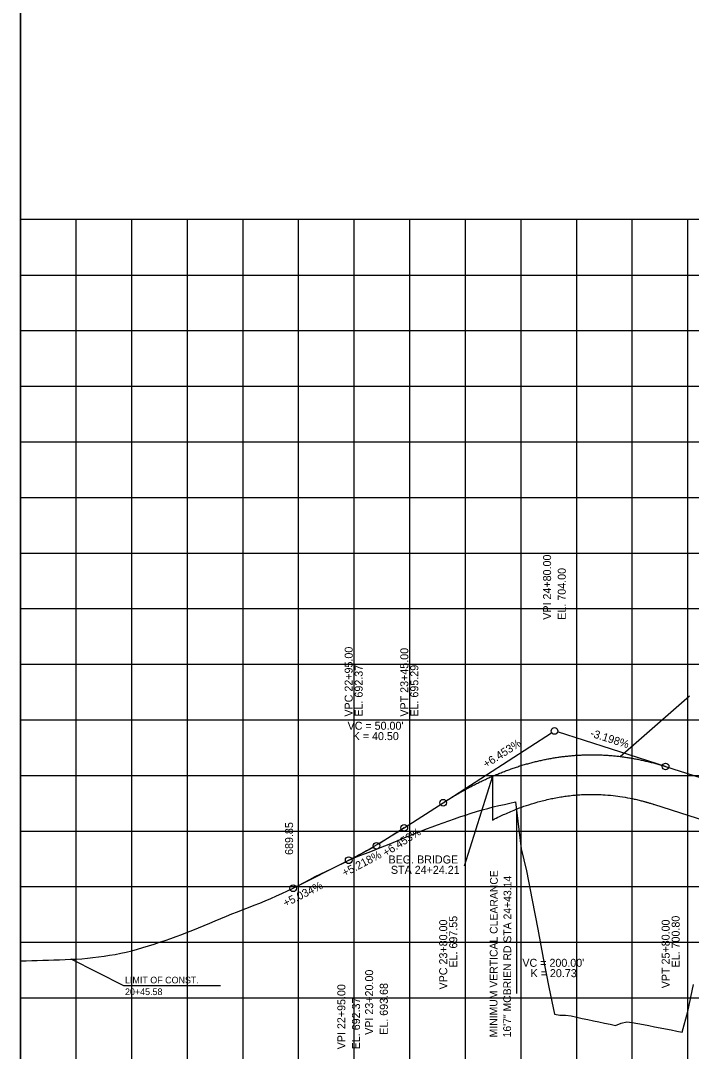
# Model space of a CAD drawing. Extents: x -7164 to 2214450, y -19642 to 253469.
# Drawn here: x 0 to 603, y -8748 to -7821 of the extents above; entities that cross this region are included whole.
import ezdxf

# ---------------------------------------------------------------- set-up
doc = ezdxf.new("R2010")
doc.units = 0
for name, color, linetype in [('DESIGN - PROFILE - Proposed', 7, 'Continuous'), ('DESIGN - PROFILE - Proposed Curve Text', 7, 'Continuous'), ('DESIGN - PROFILE - Proposed Text', 7, 'Continuous'), ('DESIGN - SCRATCH - User 1', 7, 'Continuous'), ('DESIGN - SHEET - Light Grid', 7, 'Continuous'), ('SURVEY - PROFILE - Ground Line with Text', 7, 'Continuous')]:
    doc.layers.add(name, color=color, linetype=linetype)

msp = doc.modelspace()

# ---------------------------------------------------------------- linework, layer by layer
at = {"layer": 'DESIGN - PROFILE - Proposed'}
for p, q in [((580, -8491.98), (660, -8517.56)), ((580, -8491.98), (660, -8517.56)), ((424.21, -8500.71), (424.21, -8540.08)), ((424.21, -8500.71), (424.21, -8540.08)), ((345, -8547.11), (380, -8524.53)), ((345, -8547.11), (380, -8524.53)), ((569.15, -8525.91), (654.21, -8553.11)), ((569.15, -8525.91), (654.21, -8553.11)), ((245, -8601.46), (295, -8576.28)), ((245, -8601.46), (295, -8576.28)), ((179.86, -8689.25), (92.85, -8689.25)), ((179.86, -8689.25), (92.85, -8689.25))]:
    msp.add_line(p, q, dxfattribs=at)
msp.add_lwpolyline([(92.85, -8689.25), (45.58, -8665.32)], dxfattribs=at)
msp.add_lwpolyline([(92.85, -8689.25), (45.58, -8665.32)], dxfattribs=at)
for points in [[(380, -8524.53), (384, -8521.98), (388, -8519.52), (392, -8517.13), (396, -8514.82), (400, -8512.59), (404, -8510.43), (408, -8508.35), (412, -8506.35), (416, -8504.42), (420, -8502.58), (424, -8500.8), (428, -8499.11), (432, -8497.5), (436, -8495.96), (440, -8494.5), (444, -8493.11), (448, -8491.8), (452, -8490.57), (456, -8489.42), (460, -8488.35), (464, -8487.35), (468, -8486.43), (472, -8485.58), (476, -8484.81), (480, -8484.13), (484, -8483.51), (488, -8482.98), (492, -8482.52), (496, -8482.14), (500, -8481.84), (504, -8481.61), (508, -8481.46), (512, -8481.39), (516, -8481.39), (520, -8481.48), (524, -8481.64), (528, -8481.87), (532, -8482.19), (536, -8482.58), (540, -8483.05), (544, -8483.59), (548, -8484.21), (552, -8484.91), (556, -8485.69), (560, -8486.55), (564, -8487.48), (568, -8488.49), (572, -8489.57), (576, -8490.74), (580, -8491.98)], [(380, -8524.53), (384, -8521.98), (388, -8519.52), (392, -8517.13), (396, -8514.82), (400, -8512.59), (404, -8510.43), (408, -8508.35), (412, -8506.35), (416, -8504.42), (420, -8502.58), (424, -8500.8), (428, -8499.11), (432, -8497.5), (436, -8495.96), (440, -8494.5), (444, -8493.11), (448, -8491.8), (452, -8490.57), (456, -8489.42), (460, -8488.35), (464, -8487.35), (468, -8486.43), (472, -8485.58), (476, -8484.81), (480, -8484.13), (484, -8483.51), (488, -8482.98), (492, -8482.52), (496, -8482.14), (500, -8481.84), (504, -8481.61), (508, -8481.46), (512, -8481.39), (516, -8481.39), (520, -8481.48), (524, -8481.64), (528, -8481.87), (532, -8482.19), (536, -8482.58), (540, -8483.05), (544, -8483.59), (548, -8484.21), (552, -8484.91), (556, -8485.69), (560, -8486.55), (564, -8487.48), (568, -8488.49), (572, -8489.57), (576, -8490.74), (580, -8491.98)], [(295, -8576.28), (296, -8575.76), (297, -8575.24), (298, -8574.71), (299, -8574.18), (300, -8573.64), (301, -8573.11), (302, -8572.57), (303, -8572.03), (304, -8571.49), (305, -8570.94), (306, -8570.4), (307, -8569.85), (308, -8569.29), (309, -8568.74), (310, -8568.18), (311, -8567.62), (312, -8567.06), (313, -8566.49), (314, -8565.93), (315, -8565.36), (316, -8564.78), (317, -8564.21), (318, -8563.63), (319, -8563.05), (320, -8562.47), (321, -8561.88), (322, -8561.3), (323, -8560.71), (324, -8560.11), (325, -8559.52), (326, -8558.92), (327, -8558.32), (328, -8557.72), (329, -8557.12), (330, -8556.51), (331, -8555.9), (332, -8555.29), (333, -8554.67), (334, -8554.06), (335, -8553.44), (336, -8552.82), (337, -8552.19), (338, -8551.57), (339, -8550.94), (340, -8550.3), (341, -8549.67), (342, -8549.03), (343, -8548.39), (344, -8547.75), (345, -8547.11)], [(295, -8576.28), (296, -8575.76), (297, -8575.24), (298, -8574.71), (299, -8574.18), (300, -8573.64), (301, -8573.11), (302, -8572.57), (303, -8572.03), (304, -8571.49), (305, -8570.94), (306, -8570.4), (307, -8569.85), (308, -8569.29), (309, -8568.74), (310, -8568.18), (311, -8567.62), (312, -8567.06), (313, -8566.49), (314, -8565.93), (315, -8565.36), (316, -8564.78), (317, -8564.21), (318, -8563.63), (319, -8563.05), (320, -8562.47), (321, -8561.88), (322, -8561.3), (323, -8560.71), (324, -8560.11), (325, -8559.52), (326, -8558.92), (327, -8558.32), (328, -8557.72), (329, -8557.12), (330, -8556.51), (331, -8555.9), (332, -8555.29), (333, -8554.67), (334, -8554.06), (335, -8553.44), (336, -8552.82), (337, -8552.19), (338, -8551.57), (339, -8550.94), (340, -8550.3), (341, -8549.67), (342, -8549.03), (343, -8548.39), (344, -8547.75), (345, -8547.11)]]:
    msp.add_spline(points, degree=3, dxfattribs=at)
msp.add_open_spline([(424.21, -8540.08), (429.46, -8537.4), (434.77, -8534.92), (447.1, -8529.72), (454.15, -8527.15), (464.79, -8523.92), (468.35, -8522.95), (475.5, -8521.22), (479.09, -8520.46), (486.29, -8519.16), (489.9, -8518.62), (497.12, -8517.77), (500.73, -8517.46), (507.97, -8517.07), (511.59, -8516.98), (518.83, -8517.05), (522.43, -8517.19), (533.29, -8517.98), (540.53, -8518.96), (551.33, -8521.08), (554.92, -8521.9), (559.37, -8523.05), (560.48, -8523.35), (561.59, -8523.65), (562.04, -8523.78), (562.27, -8523.84), (562.88, -8524.02), (563.3, -8524.14), (565.46, -8524.77), (567.36, -8525.35), (569.45, -8526)], degree=3, dxfattribs=at)
msp.add_open_spline([(424.21, -8540.08), (429.46, -8537.4), (434.77, -8534.92), (447.1, -8529.72), (454.15, -8527.15), (464.79, -8523.92), (468.35, -8522.95), (475.5, -8521.22), (479.09, -8520.46), (486.29, -8519.16), (489.9, -8518.62), (497.12, -8517.77), (500.73, -8517.46), (507.97, -8517.07), (511.59, -8516.98), (518.83, -8517.05), (522.43, -8517.19), (533.29, -8517.98), (540.53, -8518.96), (551.33, -8521.08), (554.92, -8521.9), (559.37, -8523.05), (560.48, -8523.35), (561.59, -8523.65), (562.04, -8523.78), (562.27, -8523.84), (562.88, -8524.02), (563.3, -8524.14), (565.46, -8524.77), (567.36, -8525.35), (569.45, -8526)], degree=3, dxfattribs=at)
at = {"layer": 'DESIGN - PROFILE - Proposed Text'}
for p, q in [((539.21, -8482.95), (601.6, -8428.35)), ((539.21, -8482.95), (601.6, -8428.35)), ((380, -8524.53), (477.48, -8461.63)), ((380, -8524.53), (477.48, -8461.63)), ((580, -8491.98), (482.86, -8460.91)), ((580, -8491.98), (482.86, -8460.91)), ((424.21, -8500.71), (398.81, -8581.7)), ((424.21, -8500.71), (398.81, -8581.7)), ((446.09, -8696.08), (446.09, -8530.25)), ((446.09, -8696.08), (446.09, -8530.25)), ((345, -8547.11), (322.52, -8561.61)), ((345, -8547.11), (322.52, -8561.61)), ((295, -8576.28), (317.34, -8564.63)), ((295, -8576.28), (317.34, -8564.63))]:
    msp.add_line(p, q, dxfattribs=at)
for centre in [(480, -8460), (480, -8460), (580, -8491.98), (580, -8491.98), (380, -8524.53), (380, -8524.53), (345, -8547.11), (345, -8547.11), (320, -8563.24), (320, -8563.24), (295, -8576.28), (295, -8576.28), (295, -8576.28), (295, -8576.28), (245, -8601.46), (245, -8601.46)]:
    msp.add_circle(centre, 3, dxfattribs=at)
at = {"layer": 'DESIGN - SCRATCH - User 1'}
for p, q in [((1000, -8000), (0, -8000)), ((0, -8000), (0, -9000)), ((1000, -8000), (0, -8000)), ((0, -8000), (0, -9000))]:
    msp.add_line(p, q, dxfattribs=at)
at = {"layer": 'DESIGN - SHEET - Light Grid'}
for p, q in [((0, -6000), (0, -8500)), ((0, -6000), (0, -8500)), ((0, -9000), (0, -6500)), ((0, -9000), (0, -6500)), ((50, -9000), (50, -8000)), ((50, -9000), (50, -8000)), ((100, -9000), (100, -8000)), ((100, -9000), (100, -8000)), ((150, -9000), (150, -8000)), ((150, -9000), (150, -8000)), ((200, -9000), (200, -8000)), ((200, -9000), (200, -8000)), ((250, -9000), (250, -8000)), ((250, -9000), (250, -8000)), ((300, -9000), (300, -8000)), ((300, -9000), (300, -8000)), ((350, -9000), (350, -8000)), ((350, -9000), (350, -8000)), ((400, -9000), (400, -8000)), ((400, -9000), (400, -8000)), ((450, -9000), (450, -8000)), ((450, -9000), (450, -8000)), ((500, -9000), (500, -8000)), ((500, -9000), (500, -8000)), ((550, -9000), (550, -8000)), ((550, -9000), (550, -8000)), ((600, -9000), (600, -8000)), ((600, -9000), (600, -8000)), ((0, -8050), (1000, -8050)), ((0, -8050), (1000, -8050)), ((0, -8100), (1000, -8100)), ((0, -8100), (1000, -8100)), ((0, -8150), (1000, -8150)), ((0, -8150), (1000, -8150)), ((0, -8200), (1000, -8200)), ((0, -8200), (1000, -8200)), ((0, -8250), (1000, -8250)), ((0, -8250), (1000, -8250)), ((0, -8300), (1000, -8300)), ((0, -8300), (1000, -8300)), ((0, -8350), (1000, -8350)), ((0, -8350), (1000, -8350)), ((0, -8400), (1000, -8400)), ((0, -8400), (1000, -8400)), ((0, -8450), (1000, -8450)), ((0, -8450), (1000, -8450)), ((0, -8500), (1000, -8500)), ((0, -8500), (1000, -8500)), ((0, -8550), (1000, -8550)), ((0, -8550), (1000, -8550)), ((0, -8600), (1000, -8600)), ((0, -8600), (1000, -8600)), ((0, -8650), (1000, -8650)), ((0, -8650), (1000, -8650)), ((0, -8700), (1000, -8700)), ((0, -8700), (1000, -8700))]:
    msp.add_line(p, q, dxfattribs=at)
at = {"layer": 'SURVEY - PROFILE - Ground Line with Text'}
for points in [[(0, -8666.74), (5, -8666.62), (10, -8666.48), (15, -8666.32), (20, -8666.17), (25, -8666.03), (30, -8665.87), (35, -8665.7), (40, -8665.57), (45, -8665.33), (50, -8665.23), (55, -8664.77), (60, -8664.37), (65, -8663.8), (70, -8663.16), (75, -8662.44), (80, -8661.71), (85, -8660.88), (90, -8659.92), (95, -8658.82), (100, -8657.6), (105, -8656.26), (110, -8654.83), (115, -8653.26), (120, -8651.67), (125, -8650.05), (130, -8648.4), (135, -8646.66), (140, -8644.83), (145, -8643.07), (150, -8641.03), (155, -8639.06), (160, -8636.96), (165, -8634.86), (170, -8632.81), (175, -8630.69), (180, -8628.54), (185, -8626.43), (190, -8624.47), (195, -8622.52), (200, -8620.54), (205, -8618.65), (210, -8616.73), (215, -8614.8), (220, -8612.79), (225, -8610.6), (230, -8608.3), (235, -8606.05), (240, -8603.8), (245, -8601.46), (250, -8598.98), (255, -8596.24), (260, -8593.48), (265, -8590.87), (270, -8588.53), (275, -8586.07), (280, -8583.61), (285, -8581.29), (290, -8578.89), (295, -8576.28), (300, -8574.18), (305, -8572.05), (310, -8570.09), (315, -8568.25), (320, -8566.43), (325, -8564.32), (330, -8562.36), (335, -8560.15), (340, -8558.18), (345, -8556.2), (350, -8554.14), (355, -8552.03), (360, -8550.01), (365, -8548.08), (370, -8546.29), (375, -8544.45), (380, -8542.56), (385, -8540.78), (390, -8538.99), (395, -8537.22), (400, -8535.61), (405, -8534.01), (410, -8532.45), (415, -8530.98), (420, -8529.58), (425, -8528.3), (430, -8527.16), (435, -8526.03), (440, -8524.9), (445, -8523.81), (450, -8566.13), (455, -8585.9), (460, -8612.13), (465, -8638.25), (470, -8664.28), (475, -8690.4), (480, -8714.75), (485, -8715.68), (490, -8715.46), (495, -8716.19), (500, -8717.35)], [(0, -8666.74), (5, -8666.62), (10, -8666.48), (15, -8666.32), (20, -8666.17), (25, -8666.03), (30, -8665.87), (35, -8665.7), (40, -8665.57), (45, -8665.33), (50, -8665.23), (55, -8664.77), (60, -8664.37), (65, -8663.8), (70, -8663.16), (75, -8662.44), (80, -8661.71), (85, -8660.88), (90, -8659.92), (95, -8658.82), (100, -8657.6), (105, -8656.26), (110, -8654.83), (115, -8653.26), (120, -8651.67), (125, -8650.05), (130, -8648.4), (135, -8646.66), (140, -8644.83), (145, -8643.07), (150, -8641.03), (155, -8639.06), (160, -8636.96), (165, -8634.86), (170, -8632.81), (175, -8630.69), (180, -8628.54), (185, -8626.43), (190, -8624.47), (195, -8622.52), (200, -8620.54), (205, -8618.65), (210, -8616.73), (215, -8614.8), (220, -8612.79), (225, -8610.6), (230, -8608.3), (235, -8606.05), (240, -8603.8), (245, -8601.46), (250, -8598.98), (255, -8596.24), (260, -8593.48), (265, -8590.87), (270, -8588.53), (275, -8586.07), (280, -8583.61), (285, -8581.29), (290, -8578.89), (295, -8576.28), (300, -8574.18), (305, -8572.05), (310, -8570.09), (315, -8568.25), (320, -8566.43), (325, -8564.32), (330, -8562.36), (335, -8560.15), (340, -8558.18), (345, -8556.2), (350, -8554.14), (355, -8552.03), (360, -8550.01), (365, -8548.08), (370, -8546.29), (375, -8544.45), (380, -8542.56), (385, -8540.78), (390, -8538.99), (395, -8537.22), (400, -8535.61), (405, -8534.01), (410, -8532.45), (415, -8530.98), (420, -8529.58), (425, -8528.3), (430, -8527.16), (435, -8526.03), (440, -8524.9), (445, -8523.81), (450, -8566.13), (455, -8585.9), (460, -8612.13), (465, -8638.25), (470, -8664.28), (475, -8690.4), (480, -8714.75), (485, -8715.68), (490, -8715.46), (495, -8716.19), (500, -8717.35)], [(500, -8717.35), (505, -8718.51), (510, -8719.58), (515, -8720.62), (520, -8721.61), (525, -8722.6), (530, -8723.59), (535, -8724.77), (540, -8722.79), (545, -8721.65), (550, -8722.2), (555, -8723.06), (560, -8723.95), (565, -8724.96), (570, -8725.96), (575, -8726.94), (580, -8727.86), (585, -8728.81), (590, -8729.85), (595, -8730.87), (600, -8712.33), (605, -8688.1)], [(500, -8717.35), (505, -8718.51), (510, -8719.58), (515, -8720.62), (520, -8721.61), (525, -8722.6), (530, -8723.59), (535, -8724.77), (540, -8722.79), (545, -8721.65), (550, -8722.2), (555, -8723.06), (560, -8723.95), (565, -8724.96), (570, -8725.96), (575, -8726.94), (580, -8727.86), (585, -8728.81), (590, -8729.85), (595, -8730.87), (600, -8712.33), (605, -8688.1)]]:
    msp.add_lwpolyline(points, dxfattribs=at)

# ---------------------------------------------------------------- texts
at = {"layer": 'DESIGN - PROFILE - Proposed'}
for s, p in [('LIMIT OF CONST.', (93.85, -8687)), ('LIMIT OF CONST.', (93.85, -8687)), ('20+45.58', (93.85, -8697.5)), ('20+45.58', (93.85, -8697.5))]:
    msp.add_text(s, height=6, dxfattribs=at).set_placement(p)
at = {"layer": 'DESIGN - PROFILE - Proposed Curve Text'}
for s, p in [('VPI 24+80.00', (477, -8360)), ('VPI 24+80.00', (477, -8360)), ('EL. 704.00', (490.2, -8360)), ('EL. 704.00', (490.2, -8360)), ('689.85', (245, -8571.46)), ('689.85', (245, -8571.46)), ('VPI 23+20.00', (317, -8733.24)), ('VPI 23+20.00', (317, -8733.24)), ('VPI 22+95.00', (292, -8746.28)), ('VPI 22+95.00', (292, -8746.28)), ('EL. 693.68', (330.2, -8733.24)), ('EL. 693.68', (330.2, -8733.24)), ('EL. 692.37', (305.2, -8746.28)), ('EL. 692.37', (305.2, -8746.28))]:
    msp.add_text(s, height=7.2, rotation=90, dxfattribs=at).set_placement(p)
for s, p in [("VC = 50.00'", (293.98, -8458.89)), ("VC = 50.00'", (293.98, -8458.89)), ('K = 40.50', (298.58, -8468.21)), ('K = 40.50', (298.58, -8468.21)), ('BEG. BRIDGE', (330.82, -8579.15)), ('BEG. BRIDGE', (330.82, -8579.15)), ('STA 24+24.21', (332.96, -8588.47)), ('STA 24+24.21', (332.96, -8588.47)), ("VC = 200.00'", (451.18, -8672.06)), ("VC = 200.00'", (451.18, -8672.06)), ('K = 20.73', (458.56, -8681.38)), ('K = 20.73', (458.56, -8681.38))]:
    msp.add_text(s, height=7.2, dxfattribs=at).set_placement(p)
at = {"layer": 'DESIGN - PROFILE - Proposed Text'}
for s, rotation, p in [('VPC 22+95.00 ', 90, (298.6, -8447.11)), ('VPC 22+95.00 ', 90, (298.6, -8447.11)), ('VPT 23+45.00 ', 90, (348.6, -8447.11)), ('VPT 23+45.00 ', 90, (348.6, -8447.11)), ('EL. 692.37', 90, (307.6, -8447.11)), ('EL. 692.37', 90, (307.6, -8447.11)), ('EL. 695.29', 90, (357.6, -8447.11)), ('EL. 695.29', 90, (357.6, -8447.11)), ('-3.198%', 342.26774, (511.61, -8464.86)), ('-3.198%', 342.26774, (511.61, -8464.86)), ('+6.453%', 32.83218, (418.74, -8493.58)), ('+6.453%', 32.83218, (418.74, -8493.58)), ('+6.453%', 32.83218, (328.48, -8573.29)), ('+6.453%', 32.83218, (328.48, -8573.29)), ('+5.218%', 27.55465, (291.34, -8591.3)), ('+5.218%', 27.55465, (291.34, -8591.3)), ('+5.034%', 26.72239, (238.25, -8618.51)), ('+5.034%', 26.72239, (238.25, -8618.51)), ('EL. 697.55', 90, (392.6, -8672.77)), ('EL. 697.55', 90, (392.6, -8672.77)), ('EL. 700.80', 90, (592.6, -8672.69)), ('EL. 700.80', 90, (592.6, -8672.69)), ('VPC 23+80.00 ', 90, (383.6, -8692.47)), ('VPC 23+80.00 ', 90, (383.6, -8692.47)), ('VPT 25+80.00 ', 90, (583.6, -8691.35)), ('VPT 25+80.00 ', 90, (583.6, -8691.35))]:
    msp.add_text(s, height=7.2, rotation=rotation, dxfattribs=at).set_placement(p)
at = {"layer": 'SURVEY - PROFILE - Ground Line with Text'}
for s, p in [('MINIMUM VERTICAL CLEARANCE', (428.64, -8735.54)), ('MINIMUM VERTICAL CLEARANCE', (428.64, -8735.54)), ('16\'7" MCBRIEN RD STA 24+43.14', (440.89, -8735.57)), ('16\'7" MCBRIEN RD STA 24+43.14', (440.89, -8735.57))]:
    msp.add_text(s, height=7, rotation=89.83045, dxfattribs=at).set_placement(p)

doc.saveas('drawing.dxf')
